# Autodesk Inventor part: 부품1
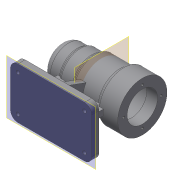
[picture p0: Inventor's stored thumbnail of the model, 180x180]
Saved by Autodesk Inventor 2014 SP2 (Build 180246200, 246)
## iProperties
Created: 2016-06
Part Number: 부품1
Material: 일반
Document SubType Name: Modeling
Designer: 201-20
Density: 1 g/cm^3
Appearance: 기본값
Author: 201-20
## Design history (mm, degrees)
sketch "스케치1"
  geometry: L1 (-56, 0)-(56, 0); L2 (56, 0)-(56, 34); L3 (56, 34)-(28, 34); L4 (28, 34)-(28, 30); L5 (28, 30)-(-11, 30); L6 (-11, 30)-(-11, 27); L7 (-11, 27)-(-31, 27); L8 (-31, 27)-(-31, 25); L9 (-31, 25)-(-56, 25); L10 (-56, 25)-(-56, 0); L11 (56, 0)-(56, 21); L12 (41, 21)-(56, 21); L13 (41, 21)-(41, 24); L14 (41, 24)-(-13, 24); L15 (-13, 24)-(-13, 21); L16 (-13, 21)-(-25, 21); L17 (-25, 21)-(-25, 17.5); L18 (-25, 17.5)-(-43, 17.5); L19 (-43, 17.5)-(-43, 16); L20 (-43, 16)-(-47, 16); L21 (-47, 16)-(-47, 10.5); L22 (-47, 10.5)-(-50, 10.5); L23 (-50, 10.5)-(-50, 0); 2 further points
  constraints: 46 end point, 12 parallel, 9 perpendicular, 2 point on line, 1 coincident, 1 horizontal, 1 midpoint
  dimensions: "d0" = 112 distance of L1.start L1.end; "d1" = 68 diameter of L3 L1; "d2" = 60 diameter of L5 L1; "d3" = 54 diameter of L7 L1; "d4" = 50 diameter of L9 L1; "d5" = 25 distance of L8.end L9.end; "d6" = 45 distance from line of L6.end L10; "d7" = 84 distance from line of L4.end L10; "d8" = 42 diameter of L12 L1; "d9" = 48 diameter of L14 L1; "d10" = 42 diameter of L16 L1; "d11" = 35 diameter of L18 L1; "d12" = 32 diameter of L20 L1; "d13" = 21 diameter of L22 L1; "d14" = 3 distance of L21.end L22.end; "d15" = 15 distance of L12.start L11.end; "d16" = 54 distance of L13.end L14.end; "d17" = 12 distance of L15.end L16.end; "d18" = 18 distance of L17.end L18.end; "d19" = 4 distance of L19.end L20.end; "d20" = 112 distance from line of L2.end L10
revolve "회전1" sketch "스케치1" stored, may be unused: angle "d21" = 90 deg
fillet "모깎기1" dims "d22" = 10
fillet "모깎기2" dims "d23" = 3
sketch "스케치2" dims "d24" = 52
  geometry: 3 further points
  constraints: 1 coincident, 1 vertical alignment, 2 other
hole "구멍1" sketch "스케치2" at (0, 26) diameter "d25" = 3.242; stored, may be unused: countersink angle "d29" = 90 deg, drill point angle "d31" = 118 deg; dims "d26" = 8, "d27" = 4, "d28" = 2, "d30" = 11
node "작업 평면1"
sketch "스케치3"
  geometry: L1 (-56, 34)-(-56, -34) reference; L2 (-56, 35)-(56, 35); L3 (56, 35)-(56, -35); L4 (56, -35)-(-56, -35); L5 (-56, -35)-(-56, 35); 2 further points
  constraints: 8 end point, 2 parallel, 1 horizontal, 1 horizontal alignment, 1 midpoint, 1 perpendicular
  dimensions: "d36" = 112 distance of L3.end L4.end; "d37" = 70 distance of L2.end L3.end
extrude "돌출1" join sketch "스케치3" distance "d38" = 10; taper "d39" = 0 deg
sketch "스케치4"
  geometry: L1 (46, -25)-(-46, -25); L2 (-46, -25)-(-46, 25); L3 (-46, 25)-(46, 25); L4 (46, 25)-(46, -25); 3 further points
  constraints: 8 end point, 2 midpoint, 2 parallel, 1 horizontal, 1 horizontal alignment, 1 perpendicular, 1 vertical alignment
  dimensions: "d40" = 92 distance of L2.end L3.end; "d41" = 50 distance of L1.end L2.end
hole "구멍2" sketch "스케치4" at (-46, -25), (46, -25), (-46, 25), (46, 25) diameter "d42" = 5; stored, may be unused: countersink angle "d46" = 90 deg, drill point angle "d48" = 118 deg; dims "d43" = 8, "d44" = 9, "d45" = 4, "d47" = 11
fillet "모깎기3" dims "d49" = 10
sketch "스케치5"
  geometry: L1 (-36, 4)-(36, 4); L2 (36, 4)-(36, -4); L3 (36, -4)-(-36, -4); L4 (-36, -4)-(-36, 4); L5 (-56, -25)-(-56, 25) reference; L6 (56, 25)-(56, -25) reference; 1 further point
  constraints: 8 end point, 2 parallel, 1 horizontal, 1 perpendicular
  dimensions: "d50" = 20 distance between parallel lines of L5 L4; "d51" = 20 distance between parallel lines of L6 L2; "d52" = 8 distance between parallel lines of L3 L1; "d53" = 4 vertical distance of L1.start point (0, 0)
extrude "돌출2" join sketch "스케치5" stored distance "d54" = 10; taper "d55" = 0 deg
node "작업 평면2"
sketch "스케치6"
  geometry: L1 (-25, -60)-(25, -60) reference; L2 (-4, -60)-(-4, -33.764) reference; L3 (-35, -60)-(-35, -70) reference; L4 (-28, -60)-(-15.509, -25.68); L5 (-35, -60)-(-25, -60) reference; A1 r 30 centre (0, 0) between (4, -29.732) and (-4, -29.732) reference; 1 further point
  constraints: 2 end point, 1 point on circle, 1 point on line
  dimensions: "d57" = 110 deg angle of L5 L4; "d58" = 7 distance from line of L4.start L3
feature "리브1" sketch "스케치6" dims "d59" = 1, "d60" = 8, "d61" = 0, "d62" = 0, "d63" = 1, "d64" = 1
node "솔리드1"
pattern_circular "원형 패턴1" dims angle "d33" = 360 deg
mirror "대칭1"
other parameters: "d56" = -56
